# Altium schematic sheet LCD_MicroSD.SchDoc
size A4; Revision: B.2
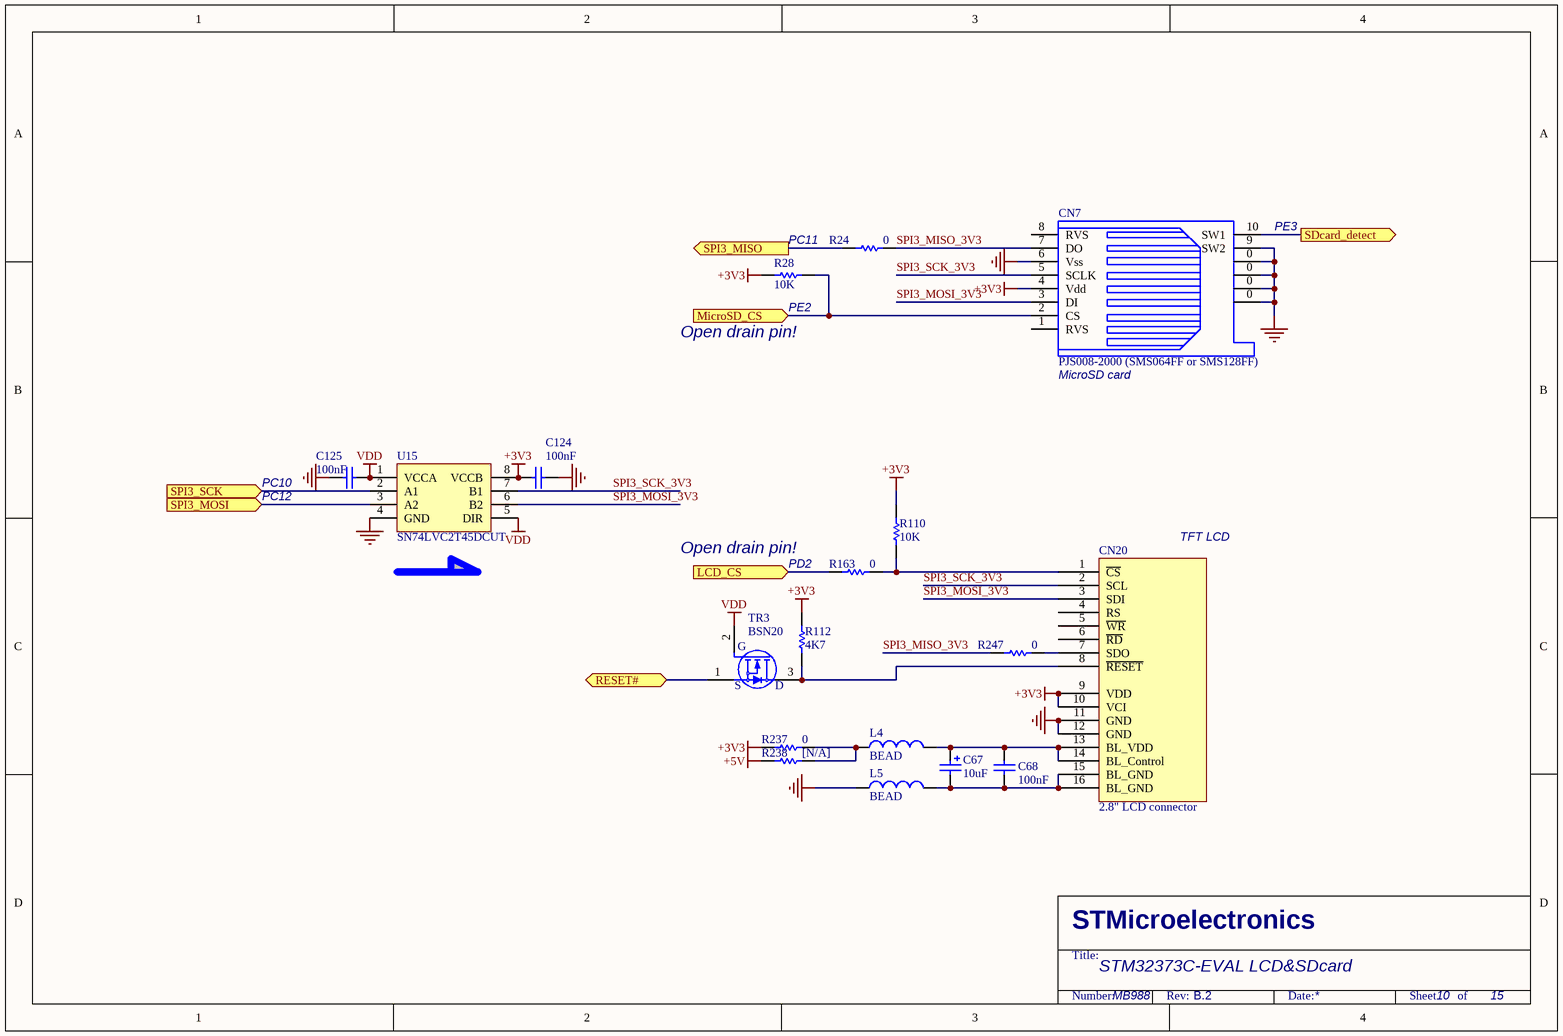
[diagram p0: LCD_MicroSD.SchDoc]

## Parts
C67  10uF  [TAN-A]
C68  100nF  [0603C]
C124  100nF  [0603C]
C125  100nF  [0603C]
CN7  PJS008-2000 (SMS064FF or SMS128FF)  [MSD(PJS008)]
CN20  2.8" LCD connector  [MB989]
L4  BEAD  [0603L]
L5  BEAD  [0603L]
R24  0  [0603R]
R28  10K  [0603R]
R110  10K  [0603R]
R112  4K7  [0603R]
R163  0  [0603R]
R237  0  [0603R]
R238  [N/A]  [0603R]
R247  0  [0603R]
TR3  BSN20  [SOT-23]
U15  SN74LVC2T45DCUT  [VSSOP8]

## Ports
LCD_CS (in), MicroSD_CS (in), RESET# (bidir), SDcard_detect (out), SPI3_MISO (out), SPI3_MOSI (in), SPI3_SCK (in)

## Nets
+3V3: C124.2 CN7.4(Vdd) CN20.9(VDD) CN20.10(VCI) R28.2 R110.2 R112.2 R237.1 U15.8(VCCB)
+5V: R238.1
GND: C124.1 C125.1 CN7.0 CN7.6(Vss) CN7.9(SW2) CN20.11(GND) CN20.12(GND) L5.1 U15.4(GND)
VDD: C125.2 TR3.2(G) U15.1(VCCA) U15.5(DIR)
LCD_CS: R163.2 ; port LCD_CS
MicroSD_CS: CN7.2(CS) R28.1 ; port MicroSD_CS
RESET#: TR3.1(S) ; port RESET#
SDcard_detect: CN7.10(SW1) ; port SDcard_detect
SPI3_MISO: R24.1 ; port SPI3_MISO
SPI3_MISO_3V3: CN7.7(DO) R24.2 R247.2
SPI3_MOSI: U15.3(A2) ; port SPI3_MOSI
SPI3_MOSI_3V3: CN7.3(DI) CN20.3(SDI) U15.6(B2)
SPI3_SCK: U15.2(A1) ; port SPI3_SCK
SPI3_SCK_3V3: CN7.5(SCLK) CN20.2(SCL) U15.7(B1)
NetC67_1: C67.1 C68.1 CN20.13(BL_VDD) CN20.14(BL_Control) L4.2
NetC67_2: C67.2 C68.2 CN20.15(BL_GND) CN20.16(BL_GND) L5.2
NetCN20_1: CN20.1(~{CS}) R110.1 R163.1
NetCN20_7: CN20.7(SDO) R247.1
NetCN20_8: CN20.8(~{RESET}) R112.1 TR3.3(D)
NetL4_1: L4.1 R237.2 R238.2

Not connected (* = marked no-connect by the designer): CN7 1(RVS) 8(RVS); CN20 4(RS) 5(~{WR}) 6(~{RD})

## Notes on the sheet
- PC11
- (near CN7) PE3
- (near R28) PE2
- (near R28) Open drain pin!
- (near CN7) MicroSD card
- PC10
- PC12
- (near R163) Open drain pin!
- PD2
- TFT LCD
- STM32373C-EVAL LCD&SDcard
- MB988
- 10
- 15

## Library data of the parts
C67 = Cap Pol1: Polarized Capacitor (Radial)
C68 = Cap: Capacitor; Value: 10nF
C124 C125 = CAP: Capacitor; Value: 100pF
CN7 = SMS016AFA5E
CN20 = ColorLCD_module
L4 L5 = Inductor: Value: 100uH
R24 R28 R110 R112 R163 R237 R238 = Res1: Resistor; Value: 1K
R247 = res1: Resistor; Value: 1K
TR3 = 2N7000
